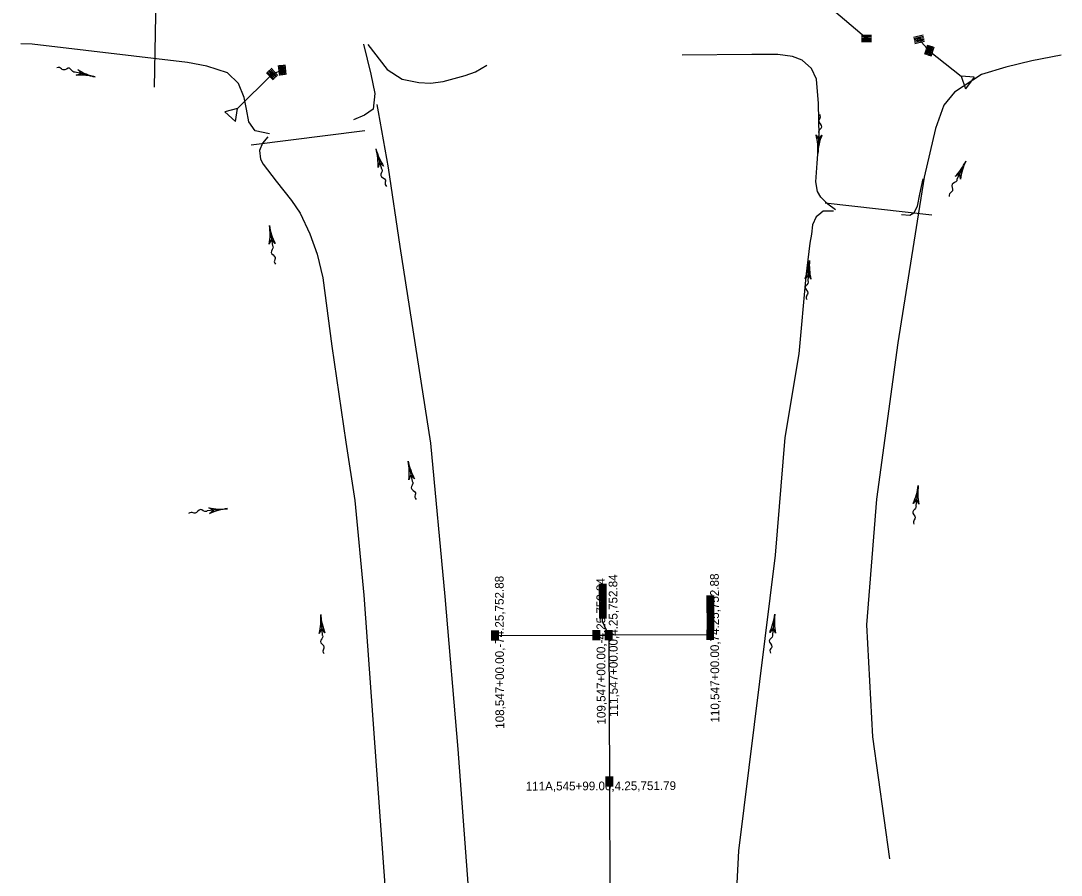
# Model space of a CAD drawing. Extents: x 593481 to 595602, y 151646 to 157396.
# Drawn here: x 593957 to 594675, y 153810 to 154399 of the extents above; entities that cross this region are included whole.
import ezdxf

# ---------------------------------------------------------------- set-up
doc = ezdxf.new("R2010")
doc.units = 0
for name, color, linetype in [('P_ALI_50_Equation', 7, 'Continuous'), ('P_DRN_Flow', 7, 'Continuous'), ('P_DRN_Inlet', 7, 'Continuous'), ('P_DRN_Pipes', 7, 'Continuous'), ('P_DRN_SS', 7, 'Continuous'), ('P_DRN_SS_UG', 7, 'Continuous')]:
    doc.layers.add(name, color=color, linetype=linetype)

msp = doc.modelspace()

# ---------------------------------------------------------------- linework, layer by layer
at = {"layer": 'P_DRN_Flow'}
for p, q in [((594007.96, 154360.42), (593994.26, 154363.85)), ((594506.81, 154307.64), (594507.66, 154321.74)), ((594201.88, 154310.74), (594205.58, 154297.1)), ((594608.95, 154302.34), (594602.78, 154289.62)), ((594128.34, 154257.93), (594130.4, 154243.95)), ((594501.06, 154233.74), (594499.92, 154219.65)), ((594224.06, 154095.33), (594226.81, 154081.47)), ((594576.12, 154078.6), (594574.4, 154064.58)), ((594099.38, 154062.53), (594085.34, 154060.93)), ((594163.75, 153989.39), (594164.77, 153975.3)), ((594477.14, 153989.64), (594475.41, 153975.61))]:
    msp.add_line(p, q, dxfattribs=at)
for points in [[(593995.06, 154361.59), (593998.65, 154362.75), (593996.03, 154365.47)], [(594505.58, 154320.54), (594507.39, 154317.22), (594509.58, 154320.3)], [(594207.16, 154298.91), (594204.39, 154301.48), (594203.3, 154297.86)], [(594605.17, 154289.95), (594604.76, 154293.7), (594601.57, 154291.69)], [(594132.19, 154245.56), (594129.74, 154248.44), (594128.23, 154244.98)], [(594502.02, 154220.82), (594500.29, 154224.17), (594498.03, 154221.14)], [(594228.52, 154083.17), (594225.93, 154085.92), (594224.6, 154082.39)], [(594576.55, 154065.66), (594574.95, 154069.08), (594572.58, 154066.14)], [(594086.89, 154059.09), (594089.84, 154061.44), (594086.43, 154063.07)], [(594166.67, 153976.78), (594164.44, 153979.82), (594162.68, 153976.48)], [(594477.56, 153976.69), (594475.97, 153980.11), (594473.59, 153977.18)]]:
    msp.add_lwpolyline(points, dxfattribs=at)
for centre, start, end in [((594018.17, 154401.11), 238.15314, 255.91546), ((593997.75, 154319.72), 75.91546, 93.67777), ((594464.93, 154310.19), 356.51249, 14.27481), ((594548.68, 154305.09), 158.75017, 176.51249), ((594242.38, 154321.71), 195.15407, 212.91639), ((594161.39, 154299.77), 357.39175, 15.15407), ((594571.19, 154320.64), 316.37324, 334.13556), ((594646.7, 154284.03), 154.13556, 171.89788), ((594086.83, 154251.81), 350.62556, 8.38788), ((594169.85, 154264.05), 188.38788, 206.1502), ((594459.24, 154237.13), 337.59352, 355.35584), ((594542.88, 154230.34), 175.35584, 193.11816), ((594265.21, 154103.52), 191.25451, 209.01683), ((594182.91, 154087.14), 353.49219, 11.25451), ((594534.48, 154083.73), 335.22094, 352.98326), ((594617.76, 154073.48), 172.98326, 190.74558), ((594094.62, 154104.22), 258.74685, 276.50917), ((594104.13, 154020.85), 96.50917, 114.27149), ((594121.9, 153986.38), 346.35512, 4.11744), ((594205.6, 153992.41), 184.11744, 201.87976), ((594435.5, 153994.78), 335.19544, 352.95776), ((594518.78, 153984.49), 172.95776, 190.72008)]:
    msp.add_arc(centre, 41.96, start, end, dxfattribs=at)
for points in [[(593994.26, 154363.85), (593993.42, 154363.74), (593990.37, 154366.45), (593986.03, 154365.27), (593983.52, 154366.87), (593981.69, 154366.68)], [(594507.66, 154321.74), (594507.4, 154322.55), (594509.5, 154326.04), (594507.54, 154330.09), (594508.66, 154332.85), (594508.13, 154334.61)], [(594205.58, 154297.1), (594206.08, 154296.43), (594205.21, 154292.45), (594208.36, 154289.24), (594208.19, 154286.26), (594209.24, 154284.76)], [(594602.78, 154289.62), (594602.72, 154288.78), (594599.45, 154286.35), (594599.72, 154281.86), (594597.64, 154279.73), (594597.45, 154277.9)], [(594130.4, 154243.95), (594130.82, 154243.22), (594129.49, 154239.37), (594132.23, 154235.81), (594131.71, 154232.88), (594132.59, 154231.26)], [(594499.92, 154219.65), (594500.17, 154218.85), (594498, 154215.4), (594499.87, 154211.31), (594498.7, 154208.57), (594499.19, 154206.8)], [(594226.81, 154081.47), (594227.27, 154080.77), (594226.13, 154076.86), (594229.05, 154073.44), (594228.68, 154070.48), (594229.63, 154068.91)], [(594574.4, 154064.58), (594574.61, 154063.76), (594572.3, 154060.41), (594574, 154056.25), (594572.72, 154053.56), (594573.13, 154051.77)], [(594085.34, 154060.93), (594084.6, 154060.53), (594080.79, 154061.99), (594077.14, 154059.36), (594074.23, 154059.98), (594072.59, 154059.16)], [(594164.77, 153975.3), (594165.14, 153974.54), (594163.52, 153970.81), (594165.99, 153967.05), (594165.25, 153964.16), (594166.01, 153962.49)], [(594475.41, 153975.61), (594475.62, 153974.8), (594473.31, 153971.44), (594475.01, 153967.28), (594473.73, 153964.59), (594474.14, 153962.8)]]:
    msp.add_spline(points, degree=3, dxfattribs=at)
at = {"layer": 'P_DRN_Inlet'}
for p, q in [((594543.76, 154389.15), (594536.89, 154389.11)), ((594543.77, 154388.25), (594536.89, 154388.21)), ((594543.77, 154387.35), (594536.9, 154387.31)), ((594543.78, 154386.45), (594536.9, 154386.41)), ((594579.49, 154389.22), (594572.78, 154387.71)), ((594579.69, 154388.35), (594572.98, 154386.83)), ((594579.89, 154387.47), (594573.18, 154385.96)), ((594580.08, 154386.59), (594573.38, 154385.08)), ((594543.78, 154385.55), (594536.91, 154385.51)), ((594543.79, 154384.65), (594536.91, 154384.61)), ((594580.28, 154385.71), (594573.58, 154384.2)), ((594580.48, 154384.83), (594573.77, 154383.32)), ((594582.52, 154382.46), (594580.42, 154375.92)), ((594583.38, 154382.19), (594581.28, 154375.64)), ((594584.23, 154381.91), (594582.14, 154375.37)), ((594585.09, 154381.64), (594582.99, 154375.09)), ((594585.95, 154381.37), (594583.85, 154374.82)), ((594586.81, 154381.09), (594584.71, 154374.54)), ((594132.87, 154360.2), (594128.17, 154365.22)), ((594133.53, 154360.82), (594128.83, 154365.83)), ((594134.19, 154361.43), (594129.48, 154366.45)), ((594135.47, 154361.53), (594134.64, 154368.36)), ((594136.36, 154361.64), (594135.53, 154368.47)), ((594137.25, 154361.75), (594136.43, 154368.57)), ((594138.15, 154361.86), (594137.32, 154368.68)), ((594139.04, 154361.97), (594138.21, 154368.79)), ((594139.93, 154362.07), (594139.11, 154368.9)), ((594130.91, 154358.35), (594126.2, 154363.37)), ((594131.56, 154358.97), (594126.86, 154363.98)), ((594132.22, 154359.59), (594127.51, 154364.6)), ((594355.95, 154010.75), (594356.05, 153986.75)), ((594356.85, 154010.76), (594356.95, 153986.76)), ((594357.75, 154010.76), (594357.85, 153986.76)), ((594358.65, 154010.76), (594358.75, 153986.76)), ((594359.55, 154010.77), (594359.65, 153986.77)), ((594360.45, 154010.77), (594360.55, 153986.77)), ((594430.24, 154002.52), (594430.34, 153978.52)), ((594431.14, 154002.53), (594431.24, 153978.53)), ((594432.04, 154002.53), (594432.14, 153978.53)), ((594432.94, 154002.53), (594433.04, 153978.53)), ((594433.84, 154002.54), (594433.94, 153978.54)), ((594434.74, 154002.54), (594434.84, 153978.54)), ((594281.86, 153971.5), (594281.84, 153978.37)), ((594282.76, 153971.5), (594282.74, 153978.38)), ((594283.66, 153971.51), (594283.64, 153978.38)), ((594284.56, 153971.51), (594284.54, 153978.39)), ((594285.46, 153971.51), (594285.44, 153978.39)), ((594286.36, 153971.52), (594286.34, 153978.39)), ((594351.86, 153971.78), (594351.84, 153978.65)), ((594352.76, 153971.78), (594352.74, 153978.65)), ((594353.66, 153971.78), (594353.64, 153978.66)), ((594354.56, 153971.79), (594354.54, 153978.66)), ((594355.46, 153971.79), (594355.44, 153978.66)), ((594356.36, 153971.79), (594356.34, 153978.67)), ((594360.36, 153971.81), (594360.34, 153978.68)), ((594361.26, 153971.81), (594361.24, 153978.69)), ((594362.16, 153971.82), (594362.14, 153978.69)), ((594363.06, 153971.82), (594363.04, 153978.69)), ((594363.96, 153971.82), (594363.94, 153978.7)), ((594364.86, 153971.83), (594364.84, 153978.7)), ((594430.36, 153972.09), (594430.34, 153978.96)), ((594431.26, 153972.09), (594431.24, 153978.96)), ((594432.16, 153972.09), (594432.14, 153978.97)), ((594433.06, 153972.1), (594433.04, 153978.97)), ((594433.96, 153972.1), (594433.94, 153978.97)), ((594434.86, 153972.1), (594434.84, 153978.98)), ((594360.74, 153870.81), (594360.72, 153877.68)), ((594361.64, 153870.81), (594361.62, 153877.69)), ((594362.54, 153870.82), (594362.52, 153877.69)), ((594363.44, 153870.82), (594363.42, 153877.69)), ((594364.34, 153870.82), (594364.32, 153877.7)), ((594365.24, 153870.83), (594365.22, 153877.7))]:
    msp.add_line(p, q, dxfattribs=at)
for points in [[(594541.33, 154387.89), (594539.33, 154387.87), (594539.34, 154385.87), (594541.34, 154385.89)], [(594577.39, 154387.47), (594575.44, 154387.03), (594575.88, 154385.08), (594577.83, 154385.52)], [(594582.97, 154379.76), (594582.36, 154377.86), (594584.26, 154377.25), (594584.87, 154379.15)], [(594138.4, 154364.34), (594138.16, 154366.33), (594136.17, 154366.09), (594136.41, 154364.1)], [(594131.61, 154362.36), (594130.24, 154363.81), (594128.78, 154362.45), (594130.15, 154360.99)], [(594357.22, 154006.03), (594357.28, 153991.49), (594359.28, 153991.49), (594359.22, 154006.04)], [(594431.51, 153997.8), (594431.57, 153983.26), (594433.57, 153983.26), (594433.51, 153997.81)], [(594285.1, 153973.95), (594285.1, 153975.95), (594283.1, 153975.94), (594283.1, 153973.94)], [(594355.1, 153974.23), (594355.1, 153976.23), (594353.1, 153976.22), (594353.1, 153974.22)], [(594363.6, 153974.26), (594363.6, 153976.26), (594361.6, 153976.25), (594361.6, 153974.25)], [(594433.6, 153974.54), (594433.59, 153976.54), (594431.59, 153976.53), (594431.6, 153974.53)], [(594363.99, 153873.26), (594363.98, 153875.26), (594361.98, 153875.25), (594361.99, 153873.25)]]:
    msp.add_lwpolyline(points, close=True, dxfattribs=at)
at = {"layer": 'P_DRN_Pipes'}
for p, q in [((594049.08, 154353.45), (594051.51, 154501.33)), ((594115.67, 154313.66), (594194.21, 154323.51)), ((594511.94, 154273.47), (594585.59, 154265.37))]:
    msp.add_line(p, q, dxfattribs=at)
at = {"layer": 'P_DRN_SS'}
for p, q in [((594614.8, 154360.25), (594605.81, 154360.9)), ((594605.81, 154360.9), (594608.67, 154352.35)), ((594614.8, 154360.25), (594608.67, 154352.35)), ((594106.22, 154338.59), (594097.46, 154336.45)), ((594104.83, 154329.69), (594097.46, 154336.45)), ((594104.83, 154329.69), (594106.22, 154338.59))]:
    msp.add_line(p, q, dxfattribs=at)
at = {"layer": 'P_DRN_SS_UG'}
for p, q in [((594540.34, 154386.88), (594491.01, 154429.16)), ((594576.63, 154386.27), (594583.61, 154378.5)), ((594583.61, 154378.5), (594605.81, 154360.9)), ((594137.29, 154365.22), (594130.19, 154362.4)), ((594130.19, 154362.4), (594106.22, 154338.59)), ((594432.6, 153975.53), (594432.59, 153978.53)), ((594284.1, 153974.95), (594354.1, 153975.22)), ((594354.1, 153975.22), (594362.6, 153975.26)), ((594432.6, 153975.53), (594362.6, 153975.26)), ((594362.6, 153975.26), (594362.98, 153874.26)), ((594362.98, 153874.26), (594363.65, 153675.25))]:
    msp.add_line(p, q, dxfattribs=at)
for points in [[(594128.33, 154321.07), (594118.39, 154323.36), (594114.1, 154329.58), (594112.46, 154338.18), (594110.81, 154346.37), (594106.98, 154355.84), (594099.39, 154363.37), (594085.14, 154367.94), (594071.84, 154370.47), (593964.7, 154383.14), (593956.75, 154383.23)], [(594193.15, 154383.13), (594198.36, 154362.45), (594201.04, 154349.12), (594199.86, 154338.2), (594194.02, 154334.04), (594186.45, 154330.91)], [(594196.16, 154382.73), (594209.59, 154365.48), (594219.98, 154358.92), (594231.38, 154356.64), (594239.5, 154356.1), (594248.18, 154357.32), (594263.31, 154361.53), (594270.5, 154363.86), (594278.32, 154368.68)], [(594519.04, 154268.76), (594513.71, 154272.64), (594508.88, 154277.46), (594506.55, 154281.49), (594505.53, 154287.97), (594506.31, 154300.86), (594507.69, 154319.69), (594507.35, 154342.04), (594505.97, 154358.95), (594502.34, 154366.34), (594495.92, 154372.11), (594489.32, 154374.5), (594479.31, 154376.01), (594461.25, 154375.97), (594413.09, 154375.58)], [(594674.76, 154375.48), (594654.48, 154371.64), (594636.55, 154367.3), (594619.8, 154362.07), (594601.08, 154349.88), (594593.78, 154340.98), (594588.06, 154324.91), (594580.14, 154291.38), (594561.92, 154177.04), (594547.4, 154069.09), (594540.49, 153982.35), (594544.44, 153905.07), (594556.18, 153820.85)], [(594202.46, 154341.41), (594203.42, 154336.48), (594210.24, 154297.69), (594218.23, 154243.42), (594239.55, 154107.82), (594249.28, 154001.84), (594258.41, 153896.56), (594265.3, 153803.82), (594275.52, 153630.37)], [(594127.29, 154319.04), (594123.56, 154314.77), (594121.4, 154309.67), (594122.26, 154303.59), (594124.01, 154300.18), (594133.09, 154288.52), (594143.62, 154275.25), (594149.46, 154266.36), (594156.23, 154252.07), (594161.18, 154238.26), (594165.2, 154221.74), (594171.35, 154174.68), (594181.15, 154108.35), (594187.24, 154068.13), (594193.38, 154002.92), (594217.22, 153675.55)], [(594579.37, 154290.04), (594576.94, 154279.64), (594575.41, 154271.26), (594573.11, 154266.46), (594570.21, 154264.92), (594564.5, 154265.28)], [(594517.63, 154267.75), (594510.41, 154267.73), (594507.44, 154265.29), (594505.7, 154263.84), (594503.23, 154258.43), (594502.33, 154251.94), (594501.27, 154245.84), (594498.53, 154222.83), (594493.59, 154169.29), (594483.93, 154111.75), (594477.34, 154030.54), (594452.1, 153826.36), (594434.68, 153487.6)], [(594362.6, 153975.26), (594358.31, 153984.76), (594358.3, 153986.76)]]:
    msp.add_lwpolyline(points, dxfattribs=at)

# ---------------------------------------------------------------- texts
at = {"layer": 'P_ALI_50_Equation'}
for s, rotation, p in [('108,547+00.00,-74.25,752.88', 90.22616, (594290.35, 153910.67)), ('109,547+00.00,-4.25,752.84', 90.22616, (594360.34, 153913.6)), ('111,547+00.00,4.25,752.84', 90.22616, (594368.82, 153918.83)), ('110,547+00.00,74.25,752.88', 90.22616, (594438.84, 153914.95)), ('111A,545+99.00,4.25,751.79', 0.20932, (594305.23, 153868.04))]:
    msp.add_text(s, height=6, rotation=rotation, dxfattribs=at).set_placement(p)

doc.saveas('drawing.dxf')
